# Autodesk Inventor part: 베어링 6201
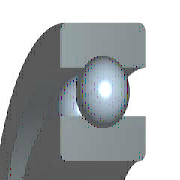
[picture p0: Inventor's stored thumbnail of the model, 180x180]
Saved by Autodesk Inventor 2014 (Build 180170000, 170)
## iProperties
Created: 2015-12
Part Number: 베어링 6201
Material: 강철, 연강
Description: 깊은 그루브 볼 베어링
Document SubType Name: Modeling
Standard: KS B 2023
Designer: mdu
Standards Organization: KS
Language: ko-KR
Size Designation: 6201 - 12 x 32 x 10
Categories: <MemberInstance><Categories><Category DisplayName="샤프트 부품" InternalName="7f7aeb1f-a693-4053-b835-cee3144e0d98" Mnemonic="SHFT"><Category DisplayName="베어링" Inter
Density: 7.86 g/cm^3
Mass: 36.8026 g
Surface Area: 42.5728 cm^2
Volume: 4.68226 cm^3
Appearance: 강철
Company: 한국ATC센터
IsCustomPart: 1
Author: mdu
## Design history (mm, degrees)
sketch "스케치" dims "d0" = 5.2 (= -0.26 x WD + 0.26 x BD)
  geometry: L1 (2.4, 11)-(7.6, 11); L2 (5, 11)-(5, 8.4); L3 (5, 11)-(5, 13.6); L4 (3.068, 9.26)-(0, 9.26); L5 (0, 6)-(10, 6); L6 (3.068, 12.74)-(0, 12.74); L7 (0, 16)-(10, 16); L8 (10, 6)-(10, 9.26); L9 (6.932, 9.26)-(10, 9.26); L10 (6.932, 12.74)-(10, 12.74); L11 (10, 16)-(10, 12.74); L12 (-1.4, 0)-(8.4, 0) reference; L13 (0, -0.3)-(0, 5.3) reference
  constraints: 22 end point, 4 point on line, 2 collinear, 2 perpendicular, 2 symmetric about line, 1 midpoint, 1 parallel, 14 other
  dimensions: "d9" = 12 diameter of L5 L12 (= WD); "d11" = 32 diameter of L7 L12 (= BD); "d12" = 10 distance between parallel lines of L8 L13 (= KB); "d13" = 18.52 diameter of L9 L12 (= 0.326 x BD + 0.674 x WD)
revolve "본체" stored, may be unused: angle "d6" = 90 deg
revolve "볼" stored, may be unused: angle "d7" = 90 deg
pattern_circular "IDS_ARRAYBALL[SIMPL:T]" dims angle "d3" = 360 deg
body "Solid1"
fillet "모깎기1" dims "d1" = 0.6 (= KRS)
other parameters: "WD" = 12 [user parameter; used in 5 equation terms], "BD" = 32 [user parameter; used in 5 equation terms], "KB" = 10 [user parameter; used in 1 equation term], "KRS" = 0.6 [user parameter; used in 1 equation term], "d4" = 0, "d5" = 0, "d8" = 0, "d14" = 0, "d15" = 0, "BBA" = 0 [user parameter], "BC0" = 3100000 [user parameter], "BC" = 6890000 [user parameter], "BR" = 16 (= 0.5 x BD) [user parameter], "WR" = 6 (= 0.5 x WD) [user parameter]
